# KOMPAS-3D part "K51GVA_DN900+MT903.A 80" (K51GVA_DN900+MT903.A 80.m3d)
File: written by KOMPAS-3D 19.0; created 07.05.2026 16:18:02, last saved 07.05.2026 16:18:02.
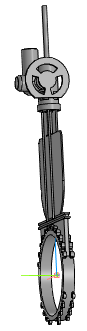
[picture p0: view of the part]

Document properties: Автор: Энергия; Полное имя файла: ..\K51GVA_DN50-DN1000+MT903.A\K51GVA_DN900+MT903.A 80.a3d

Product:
- Part/product: K51GVA_DN900+MT903.A 80
    Масса: 768.455

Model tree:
1. Операция без истории:1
